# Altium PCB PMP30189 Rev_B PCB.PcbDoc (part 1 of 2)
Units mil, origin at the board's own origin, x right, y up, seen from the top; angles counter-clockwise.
Board outline 2450 x 2800 mil, 4 copper layers (Top Layer, Signal Layer 1, Signal Layer 2, Bottom Layer), stack 82.634 mil thick; 88 components, 42 nets, 247 pads, 90 vias.
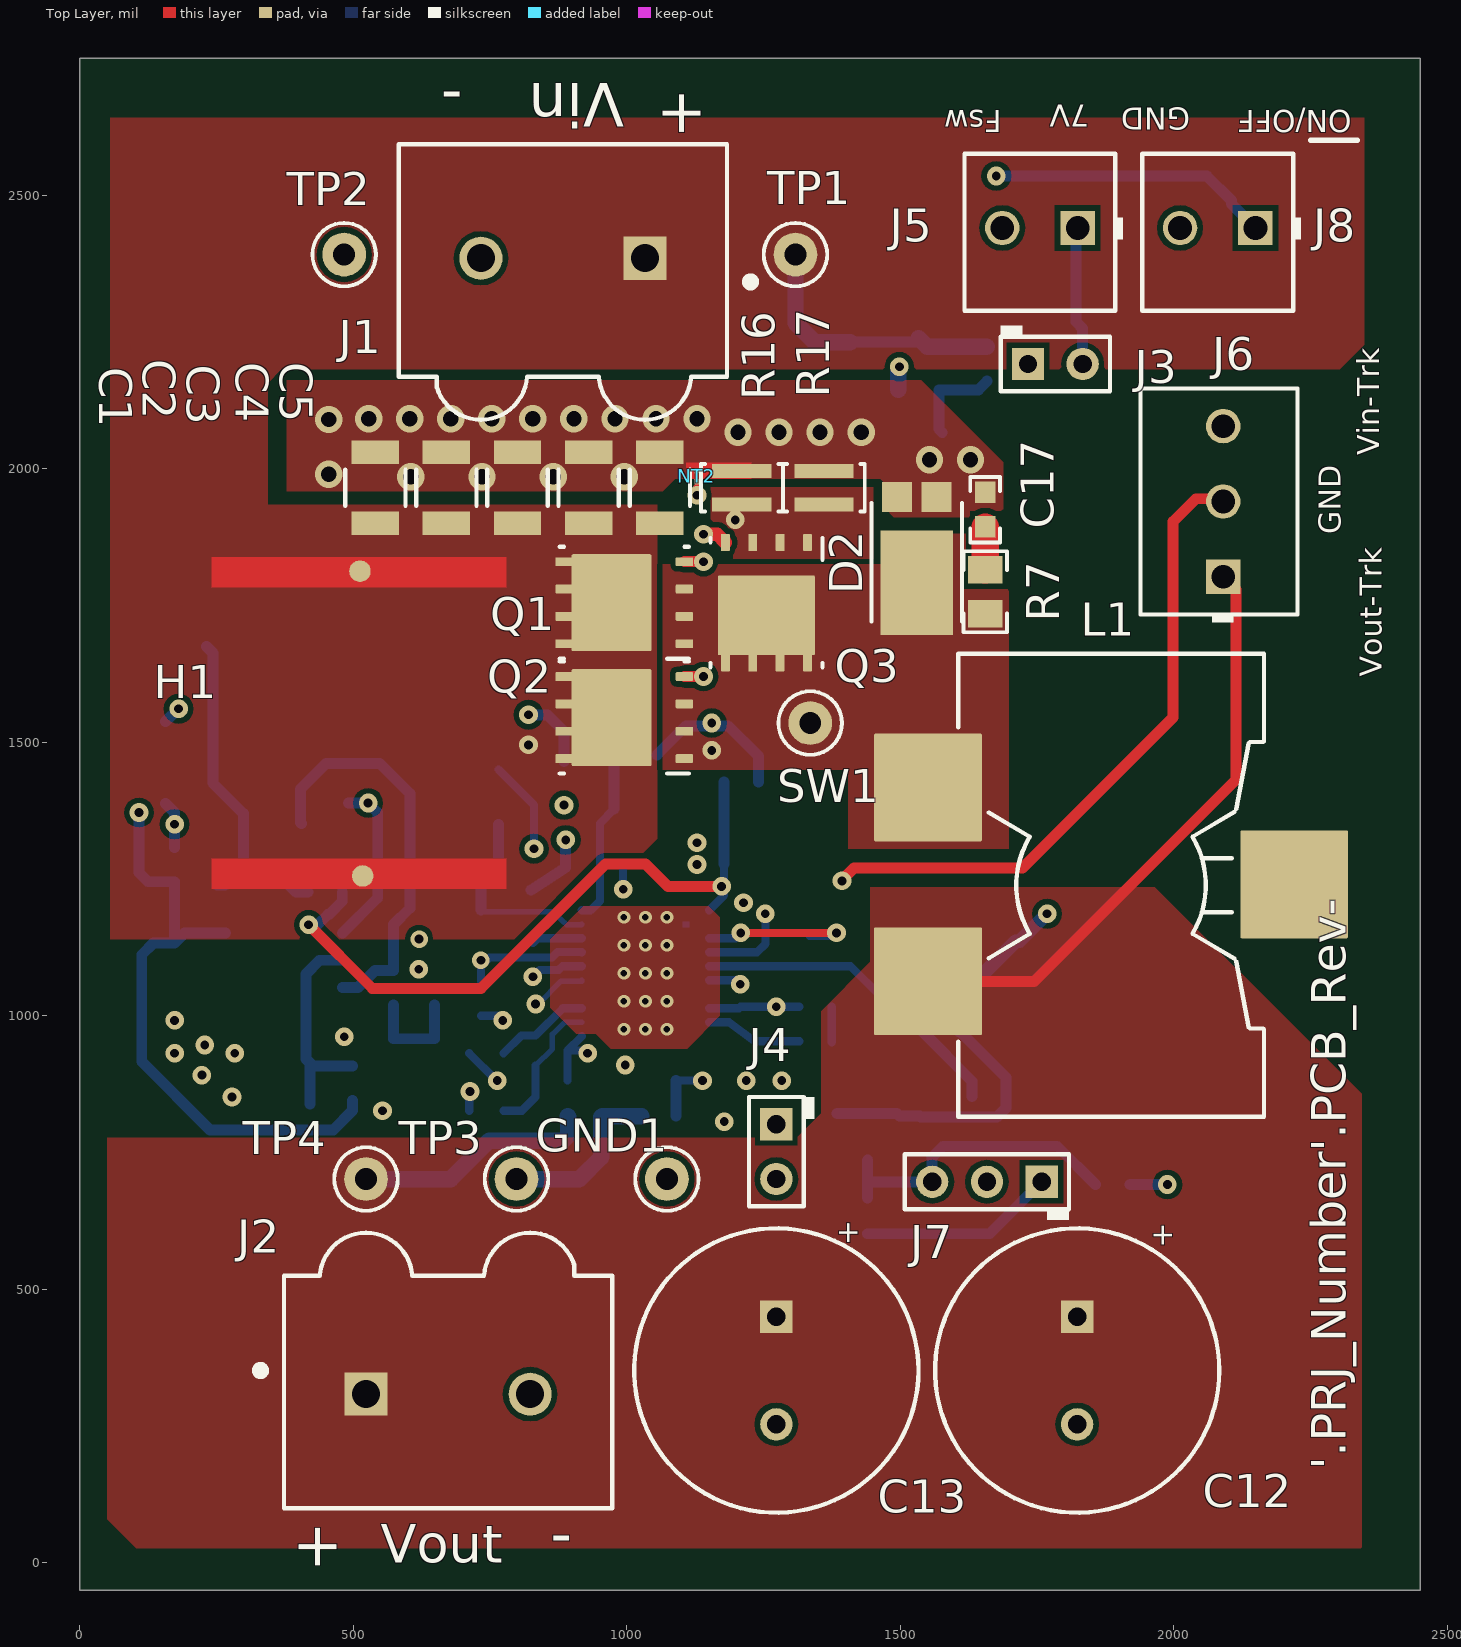
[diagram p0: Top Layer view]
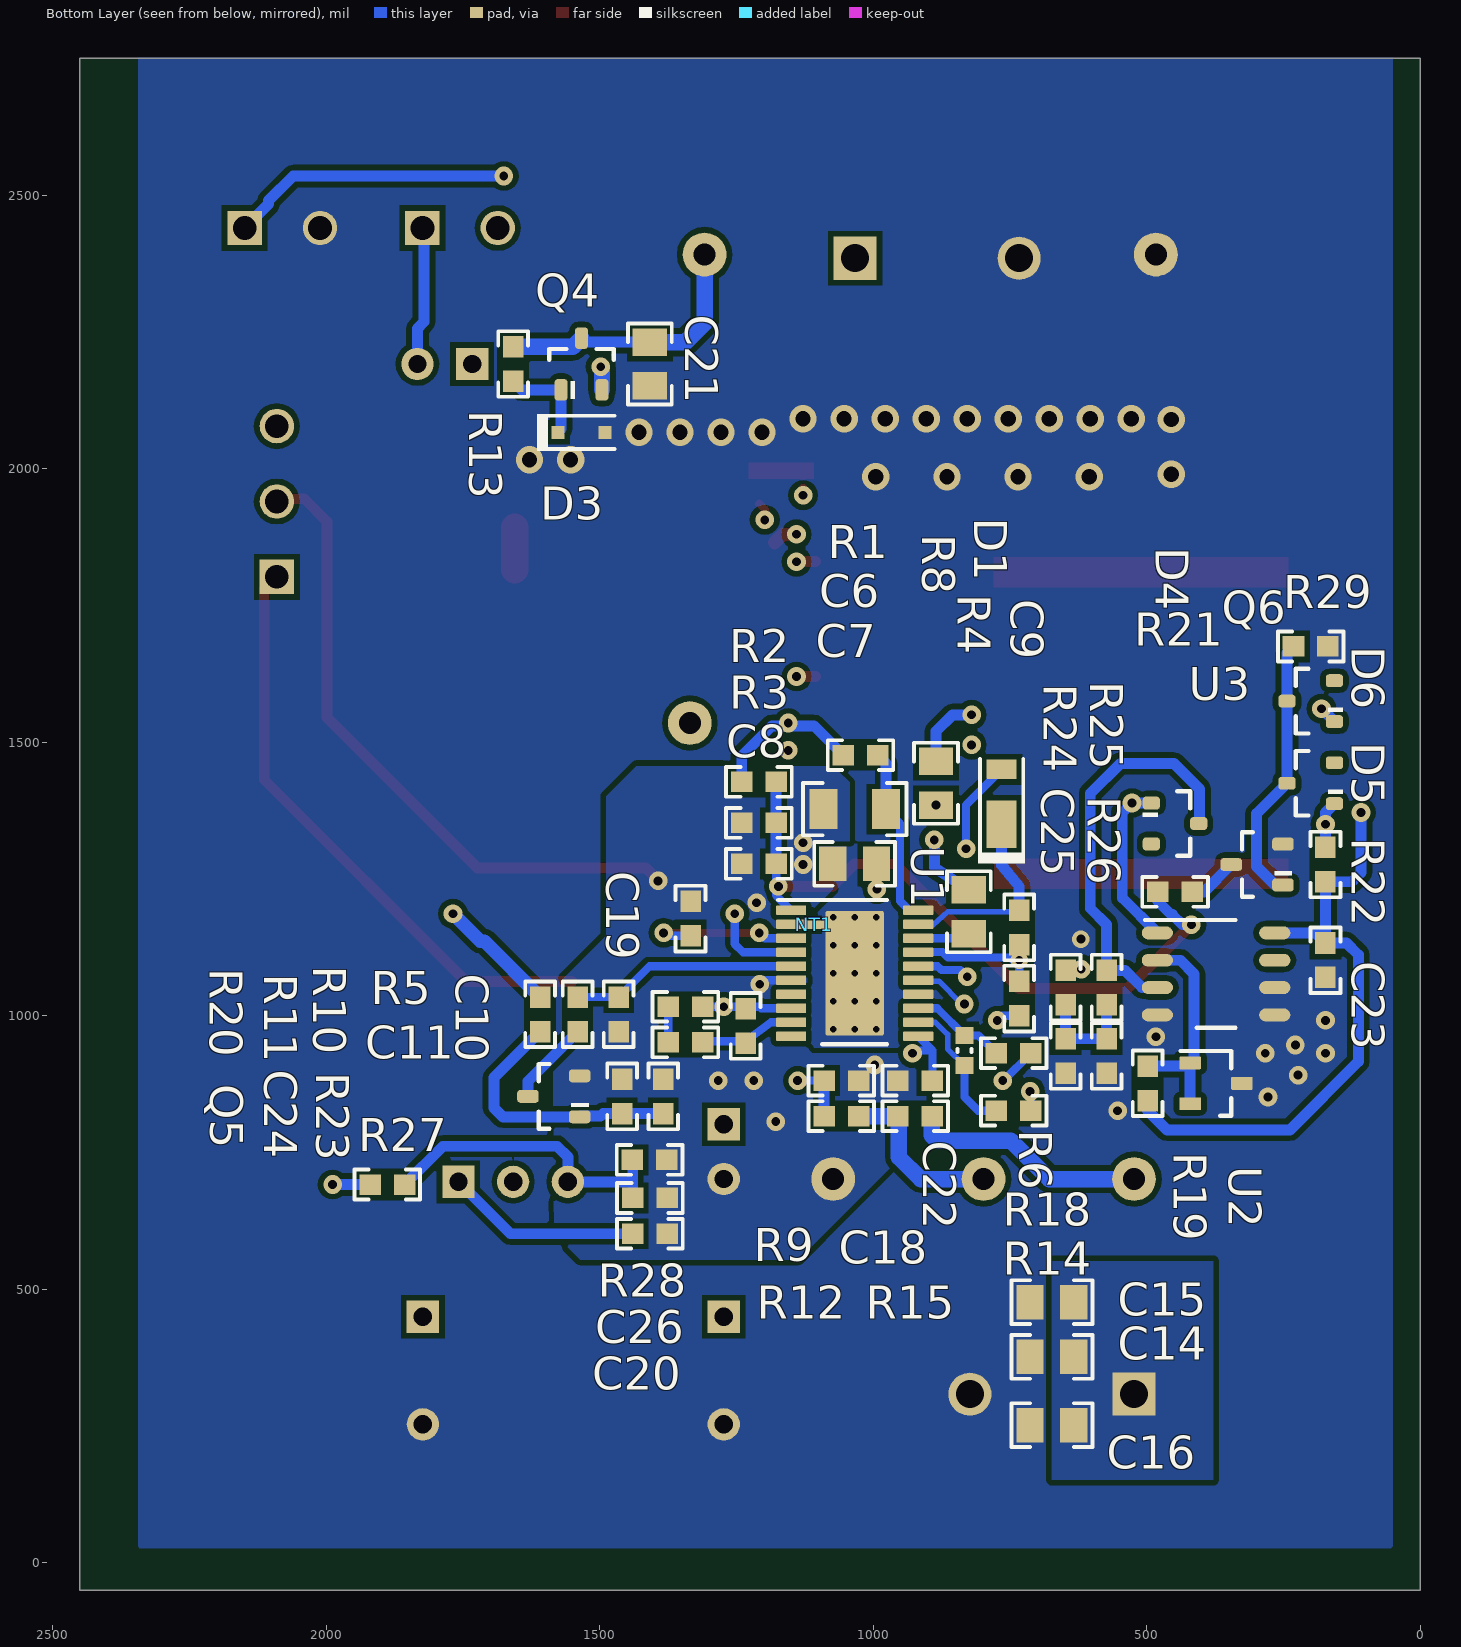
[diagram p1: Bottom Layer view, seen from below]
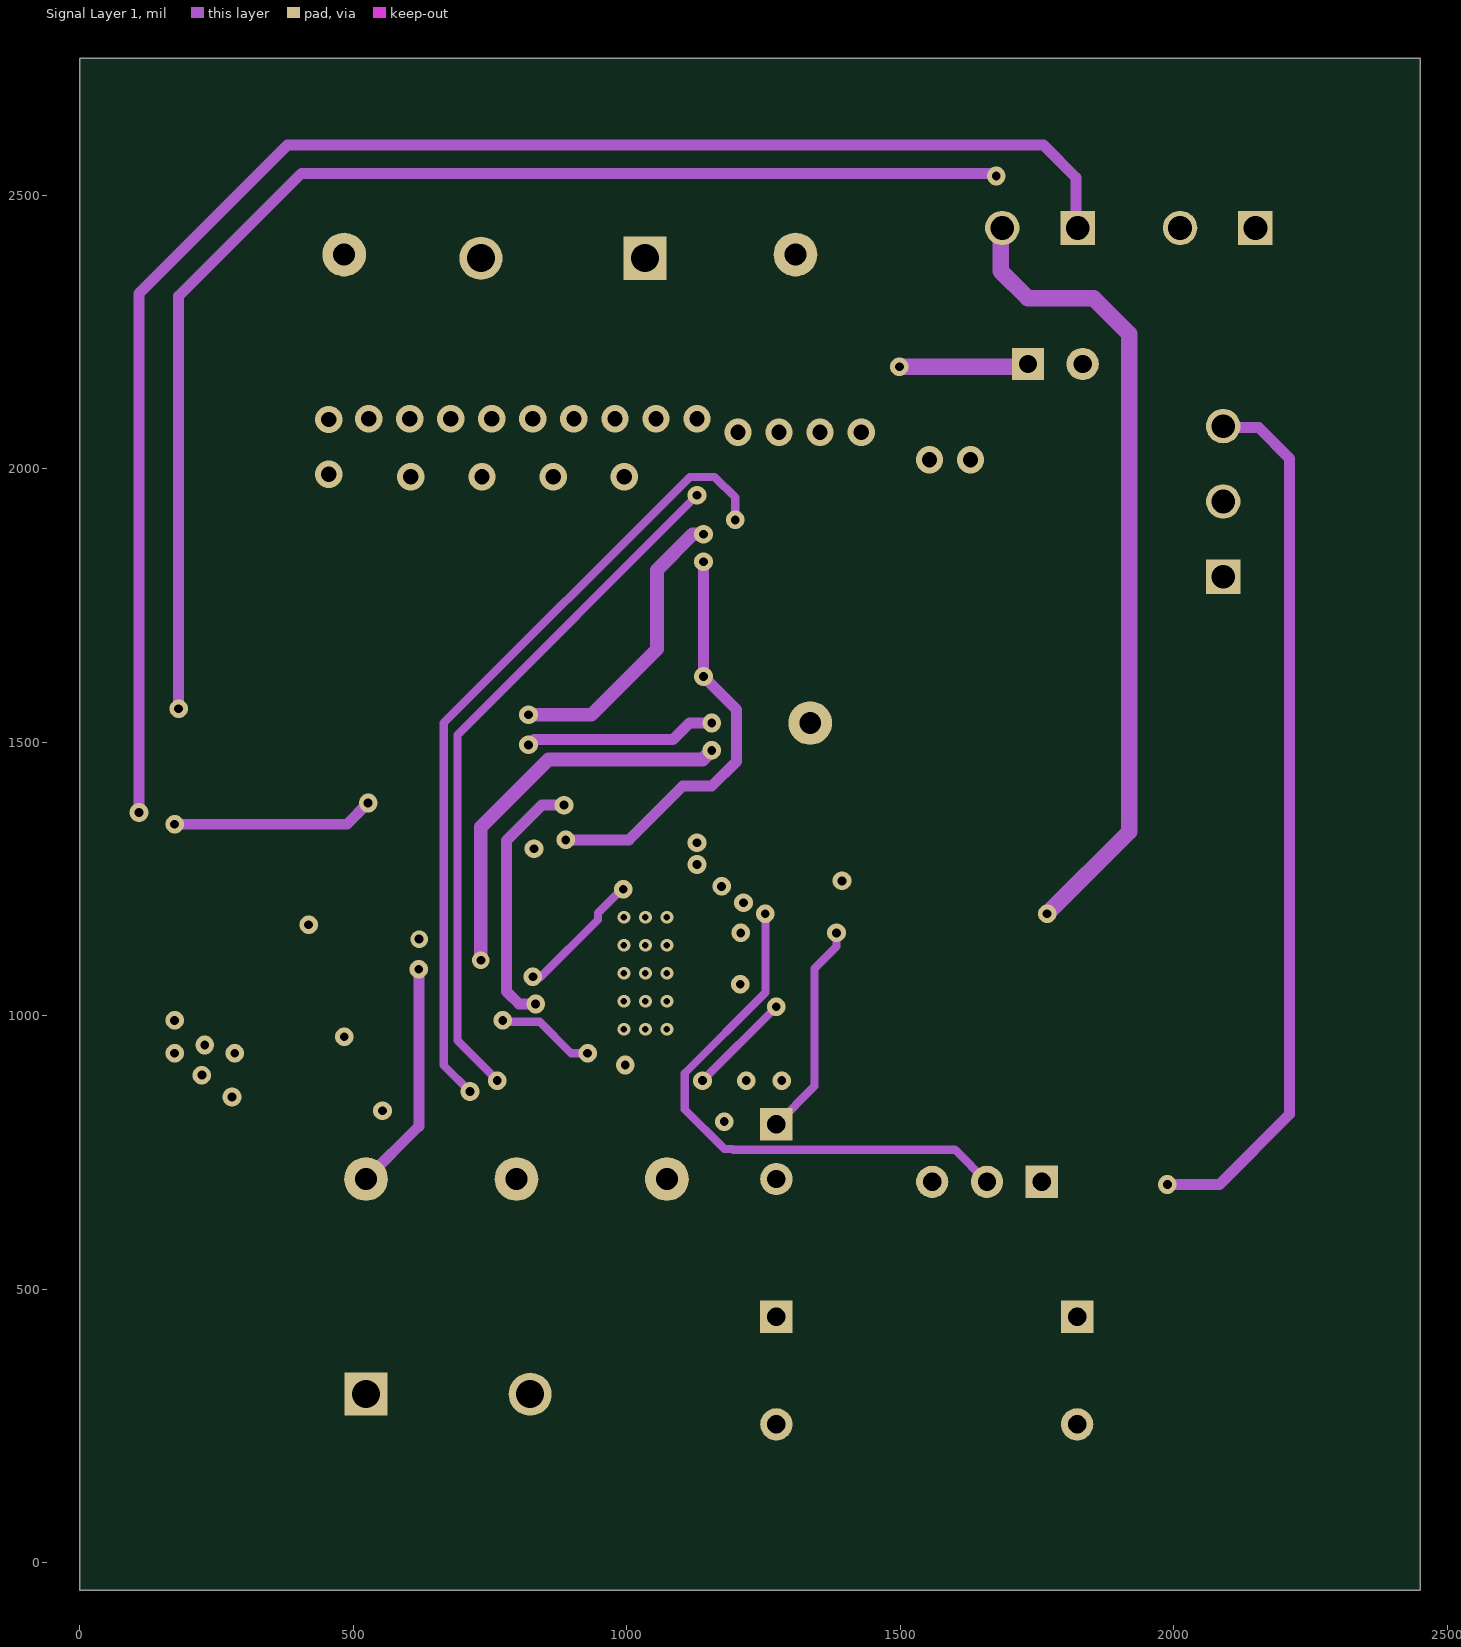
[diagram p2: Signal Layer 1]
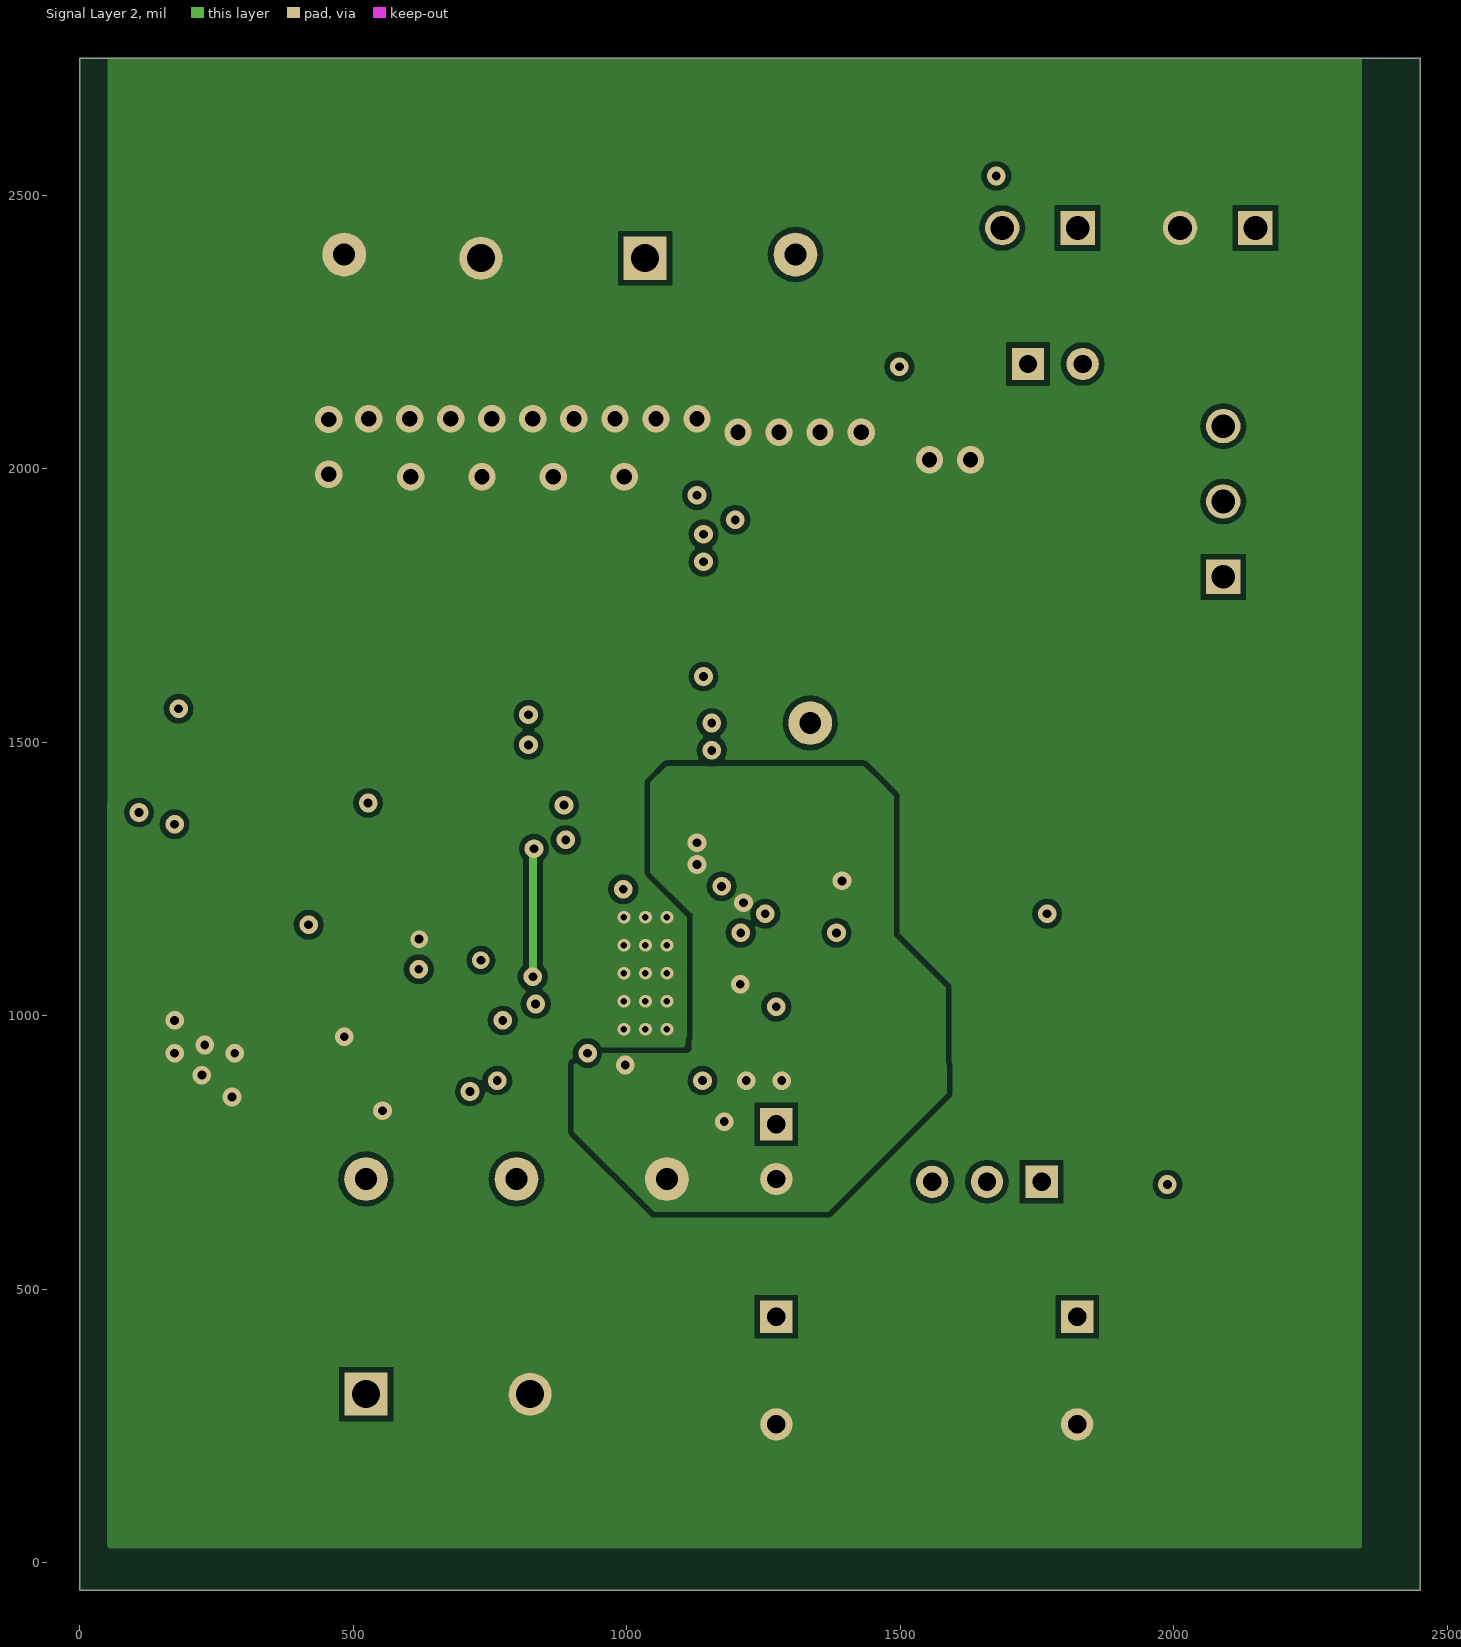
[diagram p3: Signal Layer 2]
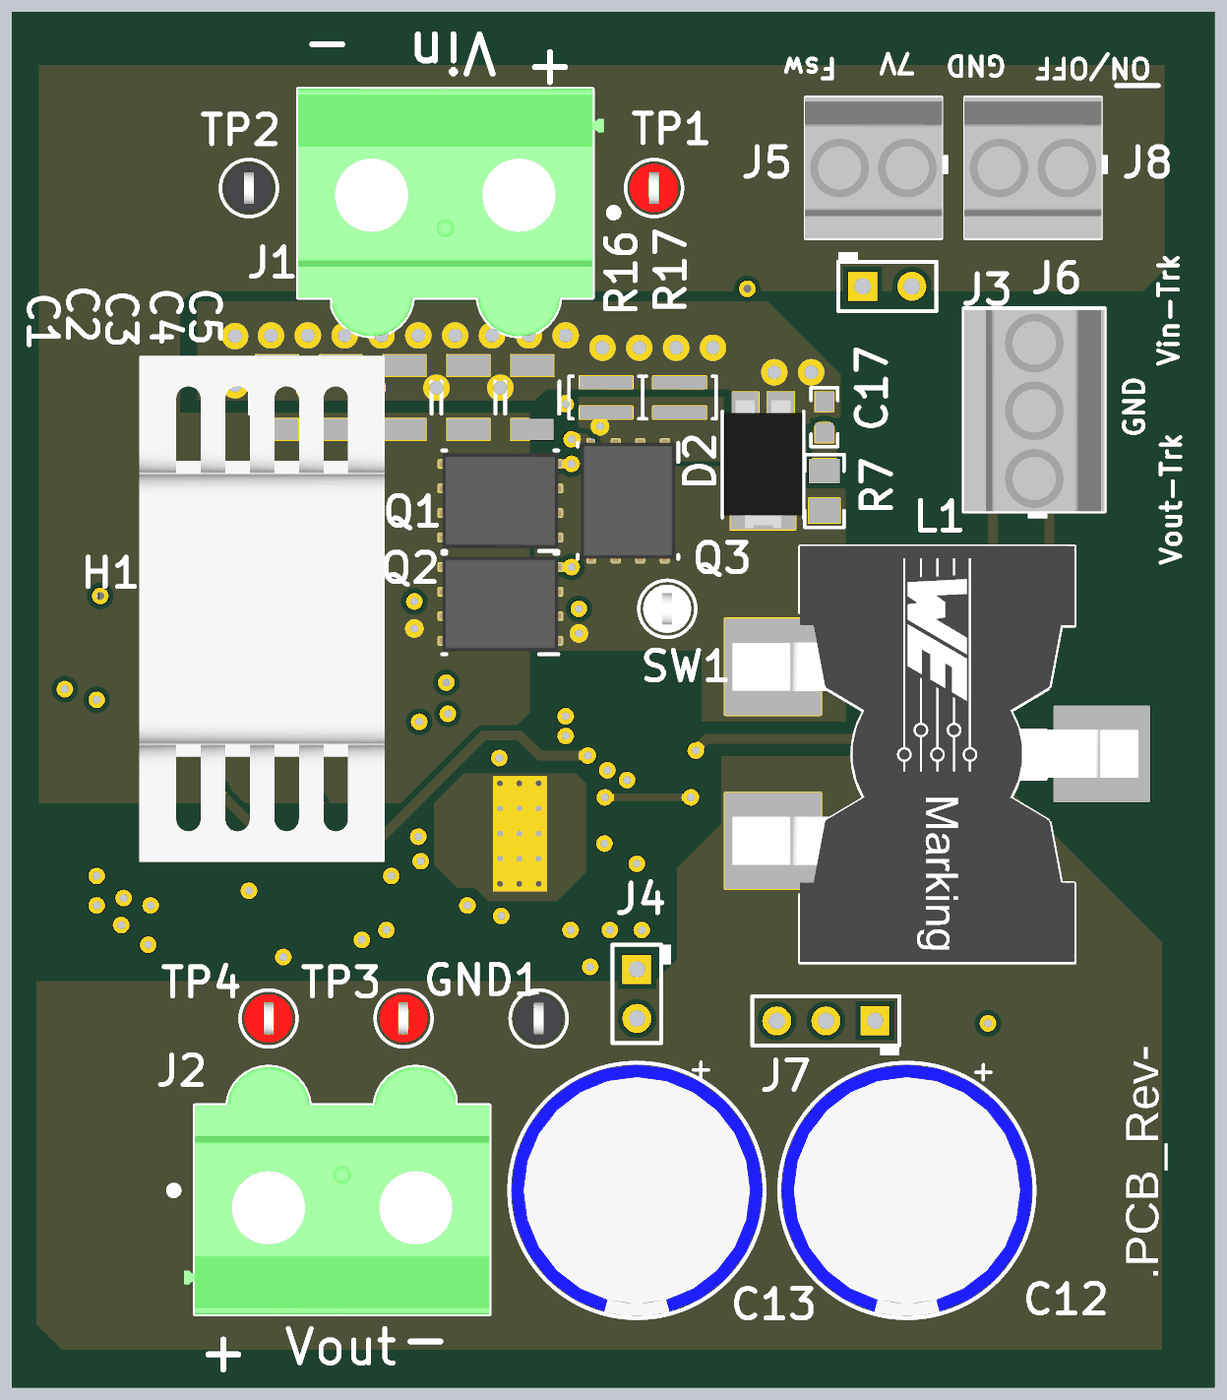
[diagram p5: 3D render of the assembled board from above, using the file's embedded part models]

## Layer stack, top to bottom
Top Solder: solder mask 0.4, Solder Resist, Dk 3.5
Top Layer: signal copper 2.8
Dielectric1: core 59.2, FR-4, Dk 4.8
Signal Layer 1: signal copper 1.417
Dielectric 3: prepreg 5, Dk 4.2
Signal Layer 2: signal copper 1.417
Dielectric 2: core 10, Dk 4.2
Bottom Layer: signal copper 2.8
Bottom Solder: solder mask 0.4, Solder Resist, Dk 3.5

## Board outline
0,-50 2450,-50 2450,2750 0,2750

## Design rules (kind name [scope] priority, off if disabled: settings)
AcuteAngle [All] p1: minimum=4.50000000000000E+0001 checktracksonly=FALSE
AssemblyTestPointUsage [All] p1: valid=2
BoardOutlineClearance BoardOutlineClearance_MountingHoles [OnCopper and InComponentClass('Mounting Holes')] p1: gap=40
BoardOutlineClearance BoardOutlineClearance_Poly [OnCopper and IsPoly] p2: gap=25
BoardOutlineClearance [OnCopper and Not InComponentClass('Logo') and not InComponentClass('FiducialMark') and not InRegion(1000,500,4000,800) and not InPoly] p3: gap=75
Clearance Clearance_Keepouts [((IsTrack Or IsArc) And Not InPoly) And IsFree and IsKeepOut vs ((IsTrack Or IsArc) And Not InPoly) And IsFree and IsKeepOut] p1: gap=0
Clearance Clearance_Poly [InPolygon] p2: gap=10
Clearance [All] p3: gap=7.87
ComponentClearance ComponentClearance_MountingHoles_FiducialMarks [InComponentClass('Mounting Holes') vs InComponentClass('FiducialMark')] p1: gap=50 collisioncheckmode=3 verticalgap=10 showdistances=FALSE
ComponentClearance ComponentClearance_Shunt [InComponentClass('Header') vs InComponentClass('Shunt')] p2: gap=0 collisioncheckmode=3 verticalgap=0 showdistances=FALSE
ComponentClearance ComponentClearance_Logo [InComponentClass('Logo')] p3: gap=50 collisioncheckmode=3 verticalgap=10 showdistances=FALSE
ComponentClearance ComponentClearance_ScrewToNut [(HasFootprint('NY PMS 440 0025 PH')) vs (HasFootprint('Keystone_1902C'))] p4: gap=5 collisioncheckmode=3 verticalgap=10 showdistances=FALSE
ComponentClearance ComponentClearance_MountingHoles [InComponentClass('Mounting Holes')] p5: gap=250 collisioncheckmode=3 verticalgap=100000 showdistances=FALSE
ComponentClearance ComponentClearance_SmallPassives [HasFootprint('0201*') or HasFootprint('0402*') or HasFootprint('0508') or HasFootprint('0603*') or HasFootprint('0612') or HasFootprint('0805*') or HasFootprint('0815*') or HasFootprint('0830*') or HasFootprint('1206*') or HasFootprint('1210*') or HasFootprint('1808*') or HasFootprint('1812*') or HasFootprint('1825*') or HasFootprint('2010*') or HasFootprint('2220*') or HasFootprint('2225*') or HasFootprint('2512*') or HasFootprint('2728*') or HasFootprint('3518*') vs HasFootprint('0201*') or HasFootprint('0402*') or HasFootprint('0508') or HasFootprint('0603*') or HasFootprint('0612') or HasFootprint('0805*') or HasFootprint('0815*') or HasFootprint('0830*') or HasFootprint('1206*') or HasFootprint('1210*') or HasFootprint('1808*') or HasFootprint('1812*') or HasFootprint('1825*') or HasFootprint('2010*') or HasFootprint('2220*') or HasFootprint('2225*') or HasFootprint('2512*') or HasFootprint('2728*') or HasFootprint('3518*')] p6: gap=14.96 collisioncheckmode=3 verticalgap=10 showdistances=FALSE
ComponentClearance ComponentClearance_THtoSMT [IsThruComponent vs IsSMTComponent] p7: gap=10 collisioncheckmode=3 verticalgap=30 showdistances=FALSE
ComponentClearance "Net Tie 10mil" [HasFootprint('Net-Tie_10mil') vs IsSMTComponent] p8: gap=0 collisioncheckmode=3 verticalgap=30 showdistances=FALSE
ComponentClearance ComponentClearance_THtoTH [IsThruComponent vs IsThruComponent] p9: gap=10 collisioncheckmode=3 verticalgap=30 showdistances=FALSE
ComponentClearance [All] p10: gap=10 collisioncheckmode=3 verticalgap=10 showdistances=FALSE
DiffPairsRouting [All] p1: maxlimit=100 minlimit=10 mostfreqgap=10 toplayer_minwidth=15 toplayer_maxwidth=15 toplayer_prefwidth=15 midlayer1_minwidth=15 midlayer1_maxwidth=15 midlayer1_prefwidth=15 midlayer2_minwidth=15 midlayer2_maxwidth=15 midlayer2_prefwidth=15 bottomlayer_minwidth=15 bottomlayer_maxwidth=15 bottomlayer_prefwidth=15 maxuncoupledlength=1000
FabricationTestPointUsage TestPointUsage [All] p1: valid=2 allowmultiple=FALSE
FabricationTestpoint Testpoint [All] p1: side=3 testpointundercomponent=TRUE minsize=40 maxsize=100 preferedsize=60 minholesize=0 maxholesize=40 preferedholesize=32 testpointgrid=1 allowsidetop=TRUE allowsidebottom=TRUE usegrid=TRUE gridtolerance=0.01
FanoutControl Fanout_LCC [IsLCC] p1: bgadir=Out bgaviamode=Centered fanoutstyle=Auto fanoutdirection=Alternating viagrid=1 // Fanout_LCC (Default Rule)
FanoutControl Fanout_BGA [IsBGA] p2: bgadir=Out bgaviamode=Centered fanoutstyle=Auto fanoutdirection=Alternating viagrid=1 // Fanout_BGA (Default Rule)
FanoutControl Fanout_Default [All] p4: bgadir=Out bgaviamode=Centered fanoutstyle=Auto fanoutdirection=Alternating viagrid=1 // Fanout_Default (Default Rule)
FanoutControl Fanout_Small [(CompPinCount < 5)] p5: bgadir=Out bgaviamode=Centered fanoutstyle=Auto fanoutdirection=OutThenIn viagrid=1 // Fanout_Small (Default Rule)
HoleSize [All] p1: absolutevalues=TRUE maxlimit=251 minlimit=11.81 maxpercent=80.000 minpercent=20.000
MinimumAnnularRing MinimumAnnularRing_ThermalPadVias [IsVia and InAnyComponent] p1: minimumring=5.91
MinimumAnnularRing [All] p2: minimumring=7.87
MinimumSolderMaskSliver MinimumSolderMaskSliver_Logo [InComponentClass('Logo') vs InComponentClass('Logo')] p1: minsoldermaskwidth=0.7
MinimumSolderMaskSliver [All] p2: minsoldermaskwidth=3.94
PlaneConnect [All] p1: planeconnectstyle=Relief reliefexpansion=10 reliefentries=4 reliefconductorwidth=10 reliefairgap=10
PolygonConnect PolygonConnect_9 [All vs IsNamedPolygon('+24V Bottom')] p1: connectstyle=Direct reliefconductorwidth=10 reliefentries=4 polygonreliefangle="90 Angle" airgapwidth=10
PolygonConnect PolygonConnect_8 [All vs IsNamedPolygon('+24V')] p2: connectstyle=Direct reliefconductorwidth=10 reliefentries=4 polygonreliefangle="90 Angle" airgapwidth=10
PolygonConnect PolygonConnect_7 [All vs IsNamedPolygon('S-GND Mid-2')] p3: connectstyle=Direct reliefconductorwidth=10 reliefentries=4 polygonreliefangle="90 Angle" airgapwidth=10
PolygonConnect PolygonConnect_6 [All vs IsNamedPolygon('S-GND Bottom')] p4: connectstyle=Direct reliefconductorwidth=10 reliefentries=4 polygonreliefangle="90 Angle" airgapwidth=10
PolygonConnect PolygonConnect_5 [All vs IsNamedPolygon('Vin')] p5: connectstyle=Direct reliefconductorwidth=10 reliefentries=4 polygonreliefangle="90 Angle" airgapwidth=10
PolygonConnect PolygonConnect_4 [All vs IsNamedPolygon('Signal Layer 1-No Net') or IsNamedPolygon('TOP_LAYER_SGND_P020')] p6: connectstyle=Direct reliefconductorwidth=10 reliefentries=4 polygonreliefangle="90 Angle" airgapwidth=10
PolygonConnect PolygonConnect_3 [All vs IsNamedPolygon('Top Layer-No Net')] p7: connectstyle=Direct reliefconductorwidth=10 reliefentries=4 polygonreliefangle="90 Angle" airgapwidth=10
PolygonConnect PolygonConnect_2 [All vs IsNamedPolygon('Switch Node')] p8: connectstyle=Direct reliefconductorwidth=10 reliefentries=4 polygonreliefangle="90 Angle" airgapwidth=10
PolygonConnect PolygonConnect_1 [All vs IsNamedPolygon('Bottom Layer-No Net')] p9: connectstyle=Direct reliefconductorwidth=10 reliefentries=4 polygonreliefangle="90 Angle" airgapwidth=10
PolygonConnect [All] p10: connectstyle=Relief reliefconductorwidth=10 reliefentries=4 polygonreliefangle="90 Angle" airgapwidth=10
RoutingVias ThermalPadVias [IsVia and InAnyComponent] p1: holewidth=7.87 width=19.68 viastyle="Through Hole" minholewidth=11.81 minwidth=23.62 maxholewidth=12.99 maxwidth=23.62
RoutingVias [All] p2: holewidth=16 width=34 viastyle="Through Hole" minholewidth=11.81 minwidth=26 maxholewidth=40 maxwidth=65
SilkToBoardRegionClearance [Not ((IsComment or IsDesignator) And (Hide <> 'False')) and not InRegion(1000,500,4000,800)] p1:
SilkToSilkClearance SilkToSilkClearance_Pb-FreeLogo [(HasFootprint('Pb-Free_Overlay_Medium') OR HasFootprint('Pb-Free_Overlay_Small')) vs (HasFootprint('Pb-Free_Overlay_Medium') OR HasFootprint('Pb-Free_Overlay_Small'))] p1: silktosilkclearance=0
SilkToSilkClearance [All] p2: silktosilkclearance=4
SilkToSolderMaskClearance SilkToComponentPadClearance [IsPad and InAnycomponent] p1: minsilkscreentomaskgap=5 clearancetoexposedcopper=TRUE
SilkToSolderMaskClearance "Silk to Solder Mask Opening" [All] p2: minsilkscreentomaskgap=4 clearancetoexposedcopper=FALSE
SolderMaskExpansion [All] p1: expansion=1.97
Width [All] p1: maxlimit=100 minlimit=6 preferedwidth=10 checkconnectedcopper=TRUE
15 further rules are at their usual default settings.

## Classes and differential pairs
component class Header: J3 J4 J7

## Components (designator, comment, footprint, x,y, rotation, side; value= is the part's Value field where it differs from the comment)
C1 "C3225X7R1H106M250AC" 1210_280 540,1965 r90 top
C2 "C3225X7R1H106M250AC" 1210_280 670,1965 r90 top
C3 "C3225X7R1H106M250AC" 1210_280 800,1965 r90 top
C4 "C3225X7R1H106M250AC" 1210_280 930,1965 r90 top
C5 "C3225X7R1H106M250AC" 1210_280 1060,1965 r90 top
C6 "GRM31MR71H105KA88L" 1206 1033.68,1377.56 r0 bottom
C7 "GRM21BR71C475KA73L" 0805_HV 1033.68,1277.56 r0 bottom
C8 "06035A101FAT2A" 0603 1208.68,1277.56 r0 bottom
C9 "GRM188R71E474KA12D" 0603 733.05,1161.38 r270 bottom
C10 "C0603C270J5GACTU" 0603 1233.05,981.38 r90 bottom
C11 "C0603C682J5RACTU" 0603 1343.05,951.38 r0 bottom
C12 "50ZLH470M12.5X20" ZLH_1250x2500 1823.05,351.38 r270 top
C13 "50ZLH470M12.5X20" ZLH_1250x2500 1273.05,351.38 r270 top
C14 "08055C105KAT2A" 0805_HV 673.05,376.38 r0 bottom
C15 "08055C105KAT2A" 0805_HV 673.05,476.38 r0 bottom
C16 "08055C104JAT2A" 0805_HV 673.05,251.38 r0 bottom
C17 "GRM1885C1H821JA01D" 0603 1655,1925 r90 top
C18 "GRM1885C1H821JA01D" 0603 923.05,881.38 r0 bottom
C19 "C1608X7R1C105K080AC" 0603 1333.68,1177.56 r90 bottom
C20 "GRM188R71C394KA88D" 0603 1408.05,601.38 r180 bottom
C21 "08055C105KAT2A" 0805_HV 1408.05,2191.38 r270 bottom
C22 "GRM1885C1H101JA01D" 0603L 833.05,936.38 r90 bottom
C23 "C1608X7R1C105K080AC" 0603 173.05,1101.38 r270 bottom
C24 "06031C103JAT2A" 0603 1458.68,852.56 r270 bottom
C25 "06031C103JAT2A" 0603 648.05,926.38 r90 bottom
C26 "06031C103JAT2A" 0603 1407.94,666.86 r0 bottom
D1 "DFLS1100-7" powerDI123 765,1400 r90 bottom
D2 "PDS760Q-13" PowerDI5 1530,1870 r270 top
D3 "MM3Z7V5B" SOD-323F 1533.05,2066.38 r180 bottom
D4 "BAS21-TP" SOT-23L 448.05,1351.38 r180 bottom
D5 "BAS21-TP" SOT-23L 200,1425 r0 bottom
D6 "BAS21-TP" SOT-23L 200,1575 r0 bottom
GND1 "5001" Keystone5001 1073.05,701.38 r0 top
H1 "573300D00010G" HEATSINK_573300D00010G 510,1535 r90 top
J1 "1732720" Phoenix_1732720 883.05,2341.38 r180 top
J2 "1732720" Phoenix_1732720 673.05,351.38 r0 top
J3 "800-10-002-10-001000" Mill-Max_800-10-002-10-001000 1783.05,2191.38 r0 top
J4 "800-10-002-10-001000" Mill-Max_800-10-002-10-001000 1273.05,751.38 r270 top
J5 "39357-0002" Molex_39357-0002 1755,2440 r180 top
J6 "39357-0003" Molex_39357-0003 2090,1940 r90 top
J7 "800-10-003-10-001000" Mill-Max_800-10-003-10-001000 1658.05,696.38 r180 top
J8 "39357-0002" Molex_39357-0002 2080,2440 r180 top
L1 "7443630700" WE-HCF_2013 1885,1240 r0 top
NT1 "Net-Tie" Net-Tie_10mil#1 1108.05,1166.38 r180 bottom net-tie
NT2 "Net-Tie" Net-Tie_10mil#2 1128.05,1986.38 r90 top net-tie
Q1 "CSD18533Q5A" DQJ0008A 995,1755 r180 top
Q2 "CSD18533Q5A" DQJ0008A 995,1545 r180 top
Q3 "CSD18533Q5A" DQJ0008A 1255,1755 r270 top
Q4 "MMBT3904LT1G" SOT-23 1533.05,2191.38 r90 bottom
Q5 "2N7002-7-F" SOT-23 1583.68,852.56 r0 bottom
Q6 "2N7002-7-F" SOT-23 298.05,1276.38 r0 bottom
R1 "CRCW06033R24FKEA" 0603 1023.05,1476.38 r180 bottom
R2 "CRCW0603100KFKEA" 0603 1208.68,1427.56 r0 bottom
R3 "RC0603FR-074K87L" 0603 1208.68,1352.56 r180 bottom
R4 "RC0805FR-072R21L" 0805_HV 825,1190 r90 bottom
R5 "RC0603FR-07294KL" 0603 1343.05,1016.38 r0 bottom
R6 "RC0603FR-07187KL" 0603 733.05,1031.38 r90 bottom
R7 "CRCW08051R21FKEA" 0805_HV 1655,1775 r270 top
R8 "RC0805FR-072R21L" 0805_HV 885,1425 r90 bottom
R9 "RC0603FR-071K65L" 0603 1058.05,881.38 r0 bottom
R10 "RC0603FR-07102KL" 0603 1465,1002.56 r90 bottom
R11 "RC0603FR-0724K9L" 0603 1540,1002.56 r90 bottom
R12 "RC0603FR-0747K5L" 0603 1058.05,816.38 r0 bottom
R13 "RC0603FR-0747K5L" 0603 1658.05,2191.38 r90 bottom
R14 "RC0603FR-07100RL" 0603 743.05,826.38 r180 bottom
R15 "RC0603FR-0749R9L" 0603 923.05,816.38 r0 bottom
R16 "PRL1632-R009-F-T1" 0612 1210,1965 r270 top
R17 "PRL1632-R009-F-T1" 0612 1360,1965 r270 top
R18 "RC0603FR-07100RL" 0603 743.05,931.38 r180 bottom
R19 "RC0603FR-076K81L" 0603 498.05,876.38 r90 bottom
R20 "CRCW060310K0FKEA" 0603 1608.68,1002.56 r90 bottom
R21 "RC0603FR-07100RL" 0603 448.05,1226.38 r0 bottom
R22 "CRCW060310K0FKEA" 0603 173.05,1276.38 r90 bottom
R23 "CRCW0603100KFKEA" 0603 1383.68,852.56 r270 bottom
R24 "CRCW0603100KFKEA" 0603 648.05,1051.38 r270 bottom
R25 "CRCW060310K0FKEA" 0603 573.05,1051.38 r90 bottom
R26 "RC0603FR-0710K5L" 0603 573.05,926.38 r90 bottom
R27 "RC0603FR-0747K5L" 0603 1888.05,691.38 r180 bottom
R28 "RC0603FR-071K58L" 0603 1408.7,736.38 r0 bottom
R29 "CRCW0603100KFKEA" 0603 200,1675 r0 bottom
SW1 "5002" Keystone5002 1335,1535 r0 top
TP1 "5000" Keystone5000 1308.05,2391.38 r0 top
TP2 "5001" Keystone5001 483.05,2391.38 r0 top
TP3 "5000" Keystone5000 798.05,701.38 r0 top
TP4 "5000" Keystone5000 523.05,701.38 r0 top
U1 "LM5117QPMH/NOPB" PWP0020A_N 1033.68,1077.56 r180 bottom
U2 "TL431AIDBZR" DBZ0003A_N 373.05,876.38 r180 bottom
U3 "LM2903VQDR" D0008A_N 373.05,1076.38 r180 bottom

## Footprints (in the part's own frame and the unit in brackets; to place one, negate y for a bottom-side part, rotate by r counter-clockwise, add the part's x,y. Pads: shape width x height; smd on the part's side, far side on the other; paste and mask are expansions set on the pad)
0603 [mm] "0603 from SM-752 data"
  rect 1x0.95 smd: 1(-0.8,0) 2(0.8,0)
  silkscreen extent -1.52,-0.69 1.52,0.69, body extent -0.87,-0.47 0.87,0.47, height 1
0603L [mm] "0603 from SM-752 data"
  rect 0.8x0.85 smd: 1(-0.7,0) 2(0.7,0)
  silkscreen extent -0.07,-0.33 0.07,0.33, body extent -0.87,-0.47 0.87,0.47, height 1
0612 [mm] "Panasonic recommended land pattern, fb97d03ed01.pdf dated April 2008"
  rect 0.65x2.75 smd: 1(-0.775,0) 2(0.775,0)
  silkscreen extent -1.1,-1.9 1.1,1.9, body extent -0.9,-1.7 0.9,1.7, height 0.85
0805_HV [mil] "0805 with 30mil clearance between pads"
  rect 50x63 smd: 1(-40,0) 2(40,0)
  silkscreen extent -74,-40 74,40, body extent -43,-29 43,29, height 57
1206 [mm] "1206 from SM-752 data"
  rect 1.3x1.85 smd: 1(-1.45,0) 2(1.45,0)
  silkscreen extent -2.4,-1.21 2.4,1.21, body extent -1.7,-0.9 1.7,0.9, height 1.35
1210_280 [mm] "SMD, 2-Leads, Body 3.6x2.8mm, Height 2.8mm"
  rect 1.1x2.2 smd: 1(-1.65,0) 2(1.65,0)
  silkscreen extent -0.84,-1.4 0.84,1.4, body extent -1.8,-1.4 1.8,1.4, height 2.8
D0008A_N [mm] "SOIC, 8-Leads, Body 4.9x3.9mm, Pitch 1.27mm, IPC Medium Density"
  oval 1.45x0.6 smd: 1(-2.725,1.905) 2(-2.725,0.635) 3(-2.725,-0.635) 4(-2.725,-1.905) 5(2.725,-1.905) 6(2.725,-0.635) 7(2.725,0.635) 8(2.725,1.905)
  silkscreen extent -3.3,-2.5 0.9,2.5, body extent -3,-2.45 3,2.45, height 1.63
DBZ0003A_N [mm] "SOT23, 3-Leads, Body 2.9x1.3mm, Pitch 0.95mm, Lead Span 2.4mm, IPC Medium Density"
  rrect17% 1x0.6 smd: 1(-1.2,0.95) 2(-1.2,-0.95) 3(1.2,0)
  silkscreen extent -1.65,-1.5 0.7,1.5, body extent -1.26,-1.46 1.26,1.46, height 0.98
DQJ0008A [mm] "SMD, 8-Leads, Body 5.75x4.9mm"
  rrect24% 0.81x0.41 smd: 1(-2.795,1.905) 2(-2.795,0.635) 3(-2.795,-0.635) 4(-2.795,-1.905) 5(2.795,-1.905) 6(2.795,-0.635) 7(2.795,0.635) 8(2.795,1.905)
  rrect8% 1.58x1.25 on Top Paste: 9(-0.38,1.45) 9(-0.38,0) 9(-0.38,-1.45) 9(1.4,1.45) 9(1.4,0) 9(1.4,-1.45)
  rrect3% 3.7x4.5 smd paste-2.5: 9(0.59,0)
  silkscreen extent -3,-2.6 3,2.6, body extent -3.13,-2.45 3.13,2.45, height 1.15
HEATSINK_573300D00010G [mm] "Aavid"
  round 1 smd: 1(-7.1,-0.175) 2(7.05,-0.05)
  Top Layer region: -6.3,6.85 -7.7,6.85 -7.7,-6.85 -6.3,-6.85
  Top Layer region: 6.3,-6.85 7.7,-6.85 7.7,6.85 6.3,6.85
  body extent -13.08,-6.35 13.08,6.35, height 10.16
Keystone5000 [mil] "For Keystone 500x miniature loop terminals"
  round 80 hole 40: 1(0,0)
  silkscreen extent -58,-58 58,58, body extent -49,-49 49,49, height 182
Keystone5001 [mil] "For Keystone 500x miniature loop terminals"
  round 80 hole 40: 1(0,0)
  silkscreen extent -58,-58 58,58, body extent -49,-49 49,49, height 182
Keystone5002 [mil] "For Keystone 500x miniature loop terminals"
  round 80 hole 40: 1(0,0)
  silkscreen extent -58,-58 58,58, body extent -49,-49 49,49, height 182
Mill-Max_800-10-002-10-001000 [mm] "Mill-Max"
  rect 1.5x1.5 hole 0.85: 1(-1.27,0)
  round 1.5 hole 0.85: 2(1.27,0)
  silkscreen extent -2.54,-1.27 2.54,1.78, body extent -2.54,-1.27 2.54,1.27, height 8.13
Mill-Max_800-10-003-10-001000 [mm] "Mill-Max"
  rect 1.5x1.5 hole 0.85: 1(-2.54,0)
  round 1.5 hole 0.85: 2(0,0) 3(2.54,0)
  silkscreen extent -3.81,-1.27 3.81,1.78, body extent -3.81,-1.27 3.81,1.27, height 8.13
Molex_39357-0002 [mm] "Terminal Block, 3.5 mm, 2x1, TH"
  rect 1.6x1.6 hole 1.1: 1(-1.75,0)
  round 1.6 hole 1.1: 2(1.75,0)
  silkscreen extent -3.86,-3.45 3.5,3.84, body extent -3.55,-3.45 3.56,3.84, height 8.51
Molex_39357-0003 [mm] "Terminal Block, 3.5 mm, 3x1, TH"
  rect 1.6x1.6 hole 1.1: 1(-3.5,0)
  round 1.6 hole 1.1: 2(0,0) 3(3.5,0)
  silkscreen extent -5.61,-3.45 5.25,3.84, body extent -5.25,-3.45 5.16,3.84, height 8.51
Net-Tie_10mil#1 [mil] "10mil net tie, no solder mask opening, no solder paste"
  rect 30x15 smd paste-5 mask-5: 1(-10,0) 2(10,0)
  Top Layer region: -6,5 6,5 6,-5 -6,-5
Net-Tie_10mil#2 [mil] "10mil net tie, no solder mask opening, no solder paste"
  rect 10x10 smd paste-5 mask-5: 1(-10,0) 2(10,0)
  Top Layer region: -6,5 6,5 6,-5 -6,-5
Phoenix_1732720 [mm] "Phoenix Contact"
  rect 2x2 hole 1.3 paste+0 mask+0.05: 1(-3.81,-1.1)
  round 2 hole 1.3 paste+0 mask+0.05: 2(3.81,-1.1)
  silkscreen extent -8.91,-6.4 7.62,6.4, body extent -8.19,-6.4 7.62,6.4, height 18.3
PowerDI5 [mm] "Diodes Inc recommended land pattern, ap02001.pdf rev 60"
  rect 1.4x1.39 smd: 1(-1.991,0.92) 2(-1.991,-0.92)
  rect 4.86x3.36 smd: 3(1.991,0)
  silkscreen extent -1.7,-2.1 3.8,2.1, body extent -2.27,-2.03 4.33,2.03, height 1.17
powerDI123 [mm] "Diodes Inc recommended land pattern, document number DS30628 Rev. 6-2"
  rect 2.2x1.4 smd: 1(-1.275,0)
  rect 0.9x1.4 smd: 2(1.275,0)
  silkscreen extent -3.1,-1.09 1.76,1.09, body extent -2.37,-0.96 1.53,0.97, height 1
PWP0020A_N [mm] "TSOP, 20-Leads, Body 6.5x4.4mm, Pitch 0.65mm, Exposed Pad, IPC Medium Density"
  rrect22% 1.4x0.45 smd: 1(-2.95,2.925) 2(-2.95,2.275) 3(-2.95,1.625) 4(-2.95,0.975) 5(-2.95,0.325) 6(-2.95,-0.325) 7(-2.95,-0.975) 8(-2.95,-1.625) 9(-2.95,-2.275) 10(-2.95,-2.925) 11(2.95,-2.925) 12(2.95,-2.275) 13(2.95,-1.625) 14(2.95,-0.975) 15(2.95,-0.325) 16(2.95,0.325) 17(2.95,0.975) 18(2.95,1.625) 19(2.95,2.275) 20(2.95,2.925)
  rrect6% 2.7x5.8 smd paste-2 mask-2: 21(0,0)
  rrect3% 3.15x4.35 on Bottom Paste: 21(0,0)
  rrect3% 3.15x4.35 on Bottom Solder: 21(0,0)
  silkscreen extent -3.55,-3.3 1.5,3.4, body extent -3.21,-3.25 3.21,3.25, height 1
SOD-323F [mm] "NXP recommended land pattern"
  rect 0.6x0.6 smd paste-0.05: 1(-1.1,0) 2(1.1,0)
  silkscreen extent -2.06,-0.86 1.53,0.86, body extent -1.35,-0.67 1.35,0.67, height 0.79
SOT-23 [mm] "SOT23, 3-Leads, Body 2.9x1.3mm, Pitch 0.95mm, Lead Span 2.5mm, IPC Medium Density"
  rrect50% 1x0.6 smd: 1(-1.2,0.95) 2(-1.2,-0.95) 3(1.2,0)
  silkscreen extent -1.62,-1.5 0.7,1.5, body extent -1.16,-1.45 1.21,1.45, height 1
SOT-23L [mm] "SOT23, 3-Leads, Body 2.9x1.3mm, Pitch 0.95mm, Lead Span 2.5mm, IPC High Density"
  rrect50% 0.8x0.6 smd: 1(-1.1,0.95) 2(-1.1,-0.95) 3(1.1,0)
  silkscreen extent -1.5,-1.5 0.7,1.5, body extent -1.16,-1.45 1.21,1.45, height 1
WE-HCF_2013 [mm] "WURTH"
  rrect2% 5x5 smd: 1(-8.5,4.5) 2(-8.5,-4.5) 3(8.5,0)
  silkscreen extent -7.1,-10.79 7.1,10.71, body extent -10.6,-10.75 10.4,10.75, height 14.02
ZLH_1250x2500 [mm] "Rubycon"
  rect 1.5x1.5 hole 0.85: 1(-2.5,0)
  round 1.5 hole 0.85: 2(2.5,0)
  silkscreen extent -6.6,-6.6 6.6,6.6, body extent -6.45,-6.49 6.49,6.49, height 26.51

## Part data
C1 C2 C3 C4 C5: "CAP, CERM, 10 µF, 50 V, +/- 20%, X7R, 1210"
C6: "CAP, CERM, 1 µF, 50 V, +/- 10%, X7R, 1206"
C7: "CAP, CERM, 4.7 µF, 16 V, +/- 10%, X7R, 0805"
C8: "CAP, CERM, 100pF, 50V, +/-1%, C0G/NP0, 0603"
C9: "CAP, CERM, 0.47uF, 25V, +/-10%, X7R, 0603"
C10: "CAP, CERM, 27 pF, 50 V, +/- 5%, C0G/NP0, 0603"
C11: "CAP, CERM, 6800 pF, 50 V, +/- 5%, X7R, 0603"
C12 C13: library part 63ZLH470M12.5X25, "CAP, AL, 470 µF, 50 V, +/- 20%, 0.027 ohm, TH"
C14 C15 C21: "CAP, CERM, 1 µF, 50 V, +/- 10%, X7R, 0805"
C16: "CAP, CERM, 0.1uF, 50V, +/-5%, X7R, 0805"
C17: "CAP, CERM, 820pF, 50V, +/-5%, C0G/NP0, 0603"
C18: "CAP, CERM, 820 pF, 50 V, +/- 5%, C0G/NP0, 0603"
C19 C23: "CAP, CERM, 1 µF, 16 V, +/- 10%, X7R, 0603"
C20: "CAP, CERM, 0.39 µF, 16 V, +/- 10%, X7R, 0603"
C22: "CAP, CERM, 100pF, 50V, +/-5%, C0G/NP0, 0603"
C24 C25 C26: "CAP, CERM, 0.01 µF, 100 V, +/- 5%, X7R, 0603"
D1: "Diode, Schottky, 100V, 1A, PowerDI123"
D2: library part PDS560-13, "Diode, Schottky, 60 V, 7 A, PowerDI5"
D3: "Diode, Zener, 7.5 V, 200 mW, SOD-323F"
D4 D5 D6: "Diode, P-N, 200V, 200A, SOT-23"
GND1 TP2: "Test Point, Miniature, Black, TH"
H1: "Heatsink, DDPAK/TO-263, SMT"
J1 J2: "Terminal Block, 2x1, 7.62mm, TH"
J3 J4: "Header, 100mil, 2x1, TH"
J5 J8: "Terminal Block, 3.5 mm, 2x1, Tin, TH"
J6: "Terminal Block, 3.5 mm, 3x1, Tin, TH"
J7: "Header, 100mil, 3x1, TH"
L1: "Inductor, Shielded Drum Core, Mn-Zn, 7 µH, 21 A, 0.005608 ohm, SMD"
NT1 NT2: "Single point connection between nets."
Q1 Q2 Q3: "MOSFET, N-CH, 60 V, 100 A, DQJ0008A (VSONP-8)"
Q4: library part "MMBT3904LT1G, ON Semiconductor", "Transistor, NPN, 40 V, 0.2 A, SOT-23"
Q5 Q6: "MOSFET, N-CH, 60 V, 0.17 A, SOT-23"
R1: "RES, 3.24 ohm, 1%, 0.1W, 0603"
R2 R23 R24 R29: "RES, 100 k, 1%, 0.1 W, 0603"
R3: "RES, 4.87 k, 1%, 0.1 W, 0603"
R4 R8: "RES, 2.21, 1%, 0.125 W, 0805"
R5: "RES, 294 k, 1%, 0.1 W, 0603"
R6: "RES, 187 k, 1%, 0.1 W, 0603"
R7: "RES, 1.21 ohm, 1%, 0.125W, 0805"
R9: "RES, 1.65 k, 1%, 0.1 W, 0603"
R10: "RES, 102 k, 1%, 0.1 W, 0603"
R11: "RES, 24.9 k, 1%, 0.1 W, 0603"
R12 R13 R27: "RES, 47.5 k, 1%, 0.1 W, 0603"
R14 R18 R21: "RES, 100, 1%, 0.1 W, 0603"
R15: "RES, 49.9, 1%, 0.1 W, 0603"
R16 R17: "RES, 0.009, 1%, 1 W, 0612"
R19: "RES, 6.81 k, 1%, 0.1 W, 0603"
R20 R22 R25: "RES, 10.0 k, 1%, 0.1 W, 0603"
R26: "RES, 10.5 k, 1%, 0.1 W, 0603"
R28: "RES, 1.58 k, 1%, 0.1 W, 0603"
SW1: "Test Point, Miniature, White, TH"
TP1 TP3 TP4: "Test Point, Miniature, Red, TH"
U1: library part LM25117QPMH/NOPB, "Wide Input Range Synchronous Buck Controller with Analog Current Monitor, PWP0020A (TSSOP-20)"
U2: "Adjustable Precision Shunt Regulator, 34 ppm / degC, 100 mA, -40 to 85 degC, 3-pin SOT-23 (DBZ), Green (RoHS & no Sb/Br)"
U3: library part LM2903AVQD, "Dual Comparator, D0008A"

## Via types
v1: diameter 34, hole 16, Top Layer to Bottom Layer, 51 vias
v2: diameter 50, hole 28, Top Layer to Bottom Layer, 21 vias
v3: diameter 23.62, hole 11.81, Top Layer to Bottom Layer, 9 vias
v4: diameter 23.62, hole 11.81, Top Layer to Bottom Layer, tented both sides, 6 vias
v5: diameter 32, hole 16, Top Layer to Bottom Layer, 2 vias
v6: diameter 34, hole 16, Top Layer to Bottom Layer, tented bottom, 1 vias

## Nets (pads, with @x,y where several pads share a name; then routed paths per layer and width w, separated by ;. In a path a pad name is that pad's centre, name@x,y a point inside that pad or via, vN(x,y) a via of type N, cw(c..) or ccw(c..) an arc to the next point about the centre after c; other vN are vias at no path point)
24V: C12.1 C13.1 C14.1 C15.1 C16.1 J2.1 J6.1 L1.2 R15.1 R24.1 TP4.1 | length 1958.1
  Top Layer w20: L1.2@1550.35,1062.83 1744.5,1062.83 2113.05,1431.38 2113.05,1779.15 J6.1@2090,1802.2
  Signal Layer 1 w20: TP4.1@523.05,701.38 619.51,797.84 v1(619.51,1085)
  Bottom Layer w30: TP4.1@523.05,701.38 678.05,701.38 748.05,771.38 883.05,771.38 893.05,781.38 893.05,814.89 R15.1@891.56,816.38
FSW_CHANGE: J5.2 R20.2 | length 1707.2
  Signal Layer 1 w30: J5.2@1683.05,2441.38 1683.05,2361.38 1733.05,2311.38 1853.05,2311.38 1918.05,2246.38 1918.05,1336.38 v1(1768.05,1186.38)
  Bottom Layer w25: R20.2@1608.68,1034.06 1711,1136.38 1718.05,1136.38 v1(1768.05,1186.38)
GND-1: C6.2 C8.2 C18.2 C19.2 C20.2 C24.1 C26.1 GND1.1 J4.2 J6.2 NT1.1 Q5.2 R3.1 R9.1 R10.1 R23.1 R28.1 U1.2 U1.6 | length 1259.4
  Top Layer w20: v1(1393.05,1246.38) 1393.05,1248.05 1415,1270 1723.05,1270 1998.05,1545 1998.05,1903.05 2040,1945 2085,1945 J6.2@2090,1940
  Bottom Layer w15: U1.6@1149.82,1064.77 1199.67,1064.77 v1(1207.05,1057.38)
  other v1: 1178.05,806.38 1218.05,881.38 1283.05,881.38 997.03,909.93 1213.05,1206.38 1128.05,1276.38 1128.05,1316.38
NetC6_1: C6.1 R1.2 U1.20 | length 323.6
  Bottom Layer w15: U1.20@917.54,1192.72 933.44,1192.72 950.59,1209.87 950.59,1351.56 C6.1@976.59,1377.56
  Bottom Layer w20: C6.1@976.59,1377.56 976.59,1461.42 R1.2@991.56,1476.38
NetC9_1: C9.1 D1.1 U1.19 | length 363.3
  Bottom Layer w10: C9.1@733.05,1192.88 735.93,1190 863.41,1190 890,1166.38 916.79,1166.38 U1.19@917.54,1167.13
  Bottom Layer w20: C9.1@733.05,1192.88 733.05,1236.19 765,1275 D1.1@765,1349.8
NetC9_2: C9.2 D2.3 L1.1 Q1.1 Q1.2 Q1.3 Q2.1 Q2.2 Q2.3 Q3.5 Q3.6 Q3.7 Q3.8 Q3.9@1255,1731.77 R6.2 R7.2 SW1.1 U1.17 | length 954.7
  Signal Layer 1 w25: v5(733.02,1101.4) 733.02,1344.87 856.46,1468.31 1138.31,1468.31 v1(1155,1485)
  Bottom Layer w15: R6.2@733.02,1062.91 v5(733.02,1101.4) ; v5@735,1092.41 748.98,1106.38 863.05,1106.38 873.05,1116.38 917.11,1116.38 U1.17@917.54,1115.95
NetC10_1: C10.1 C11.1 U1.9 | length 177.3
  Bottom Layer w15: U1.9@1149.82,988 1186.44,988 1233.05,953.33 C11.1@1315.61,953.33
NetC10_2: C10.2 R5.1 R9.2 R12.2 U1.8 | length 470
  Signal Layer 1 w15: v1(1138.05,881.38) v1(1273.05,1016.38)
  Bottom Layer w15: R9.2@1089.55,881.38 v1(1138.05,881.38) ; U1.8@1149.82,1013.59 1205.02,1013.59 1207.81,1016.38 v1(1273.05,1016.38) ; v1@1273.82,1016.38 R5.1@1315,1016.38
  Bottom Layer w20: R12.2@1089.55,816.38 R9.2@1089.55,881.38
NetC11_2: C11.2 R5.2 | length 65
  Bottom Layer w15: C11.2@1374.55,951.38 R5.2@1374.55,1016.38
NetC17_1: C17.1 R7.1 | length 78.5
  Top Layer w50: R7.1@1655,1815 C17.1@1655,1893.5
NetC18_1: C18.1 R6.1 U1.11 | length 353.7
  Signal Layer 1 w15: v1(773.05,991.38) 775.43,989.01 840.43,989.01 898.05,931.38 v1(928.05,931.38)
  Bottom Layer w15: R6.1@733.05,999.89 764.55,999.89 v1(773.05,991.38) ; C18.1@891.56,881.38 891.56,936.42 ; U1.11@917.54,962.41 891.56,936.42 ; v1(928.05,931.38) 923.01,936.42 891.56,936.42
NetC19_1: C19.1 J4.1 U1.3 | length 684.4
  Top Layer w15: v1(1208.05,1151.38) v1(1383.05,1151.38)
  Signal Layer 1 w15: J4.1@1273.05,801.38 1343.05,871.38 1343.05,1086.38 1383.05,1126.38 v1(1383.05,1151.38)
  Bottom Layer w15: U1.3@1149.82,1141.54 1198.21,1141.54 v1(1208.05,1151.38) ; C19.1@1333.68,1146.07 1377.74,1146.07 v1(1383.05,1151.38)
NetC20_1: C20.1 J7.1 | length 357.9
  Bottom Layer w20: C20.1@1439.55,601.38 1663.05,601.38 J7.1@1758.05,696.38
NetC22_1: C22.1 R14.1 U1.12 | length 259
  Bottom Layer w10: C22.1@833.05,908.82 863.68,939.45 863.68,965.76 885.92,988 U1.12@917.54,988
  Bottom Layer w15: R14.1@774.55,826.38 808.05,826.38 833.05,851.38 C22.1@833.05,908.82
NetC22_2: C22.2 R18.1 U1.13 | length 177
  Bottom Layer w15: R18.1@774.55,931.38 807.11,963.94 C22.2@833.05,963.94 882.7,1013.59 U1.13@917.54,1013.59
NetC23_1: C23.1 J3.2 J5.1 R19.1 R22.1 U3.8 | length 4272
  Signal Layer 1 w20: v1(108.05,1371.38) 108.05,2320 379.43,2591.38 1761.4,2591.38 1820.85,2531.93 J5.1@1820.85,2441.38
  Bottom Layer w20: v1(108.05,1371.38) 108.05,1261.38 124.55,1244.89 R22.1@173.05,1244.89 C23.1@173.05,1132.88 ; U3.8@265.77,1151.38 191.55,1151.38 C23.1@173.05,1132.88 ; R19.1@498.05,844.89 498.05,826.38 463.05,791.38 238.05,791.38 113.05,916.38 113.05,1111.38 134.55,1132.88 C23.1@173.05,1132.88 ; J5.1@1820.85,2441.38 1820.85,2268.59 1833.05,2256.38 J3.2@1833.05,2191.38
NetC24_2: C24.2 Q5.1 R20.1 R23.2 | length 494.1
  Bottom Layer w20: R23.2@1383.68,821.07 C24.2@1458.68,821.07 1493.37,821.07 1498.05,816.38 1535.22,816.38 Q5.1@1536.44,815.16 1676.83,815.16 1693.05,831.38 1693.05,886.7 R20.1@1608.68,971.07 R20.1@1608.05,970.44
NetC25_2: C25.2 R24.2 R25.1 R26.2 | length 199
  Bottom Layer w20: R25.1@573.05,1019.89 R26.2@573.05,957.88 C25.2@648.05,957.88 R24.2@648.05,1019.89
NetC26_2: C26.2 J7.3 R27.2 R28.2 | length 569.2
  Bottom Layer w20: C26.2@1439.44,666.86 1439.44,696.38 ; R28.2@1440.2,736.38 1439.44,735.63 1439.44,696.38 ; R27.2@1856.56,691.38 1786.56,761.38 1578.05,761.38 1558.05,741.38 J7.3@1558.05,696.38 1439.44,696.38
